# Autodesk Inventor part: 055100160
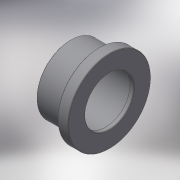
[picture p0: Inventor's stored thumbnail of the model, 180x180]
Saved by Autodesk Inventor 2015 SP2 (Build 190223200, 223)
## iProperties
Created: 2017-10
Part Number: 055100160
Material: Generic
Description: PLASSON FLANGE FLAT AD.-CEM 160
Document SubType Name: Modeling
Designer: KIM
Mass: 758.339 g
Surface Area: 1372.74 cm^2
Volume: 758.339 cm^3
Density: 1 g/cm^3
Appearance: Default
Author: KIM
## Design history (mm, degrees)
derived "055100.ipt"
feature "Solid1::055100.ipt"
tag "TaggingFeature1"
body "Solid1"
other parameters: "d0" = 92, "d1" = 185, "d3" = 144, "d4" = 13, "d5" = 86, "d6" = 213, "d8" = 1.6, "E_" = 185, "E_1" = 213, "l_" = 86, "B_" = 13, "H_" = 92
